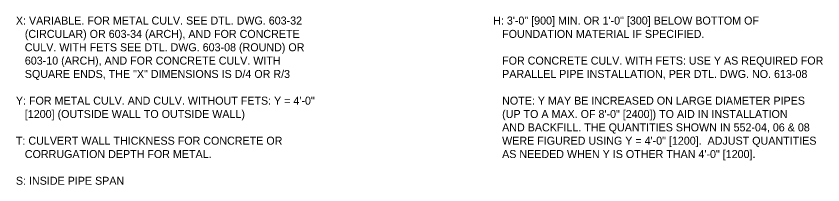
# Model space of a CAD drawing. Extents: x 49988.5 to 50021, y 49987.6 to 50011.4.
# Drawn here: x 49988.46 to 49994.5, y 50007.36 to 50008.62 of the extents above; entities that cross this region are included whole.
import ezdxf

# ---------------------------------------------------------------- set-up
doc = ezdxf.new("R2010")
doc.units = 0
doc.layers.add('Level 2', color=7, linetype='Continuous')

msp = doc.modelspace()

# ---------------------------------------------------------------- texts
at = {"layer": 'Level 2'}
for s, p in [('X: VARIABLE. FOR METAL CULV. SEE DTL. DWG. 603-32 ', (49988.456, 50008.5609)), ('H: 3\'-0" [900] MIN. OR 1\'-0" [300] BELOW BOTTOM OF', (49992.0327, 50008.5609)), ('   (CIRCULAR) OR 603-34 (ARCH), AND FOR CONCRETE ', (49988.456, 50008.4609)), ('   FOUNDATION MATERIAL IF SPECIFIED.', (49992.0327, 50008.4609)), ('   CULV. WITH FETS SEE DTL. DWG. 603-08 (ROUND) OR ', (49988.456, 50008.3609)), ('   603-10 (ARCH), AND FOR CONCRETE CULV. WITH ', (49988.456, 50008.2609)), ('   FOR CONCRETE CULV. WITH FETS: USE Y AS REQUIRED FOR', (49992.0327, 50008.2609)), ('   SQUARE ENDS, THE "X" DIMENSIONS IS D/4 OR R/3', (49988.456, 50008.1609)), ('   PARALLEL PIPE INSTALLATION, PER DTL. DWG. NO. 613-08', (49992.0327, 50008.1609)), ('Y: FOR METAL CULV. AND CULV. WITHOUT FETS: Y = 4\'-0"', (49988.456, 50007.9609)), ('   NOTE: Y MAY BE INCREASED ON LARGE DIAMETER PIPES', (49992.0327, 50007.9609)), ('   [1200] (OUTSIDE WALL TO OUTSIDE WALL)', (49988.456, 50007.8609)), ('   (UP TO A MAX. OF 8\'-0" [2400]) TO AID IN INSTALLATION', (49992.0327, 50007.8609)), ('   AND BACKFILL. THE QUANTITIES SHOWN IN 552-04, 06 & 08', (49992.0327, 50007.7609)), ('T: CULVERT WALL THICKNESS FOR CONCRETE OR', (49988.456, 50007.6609)), ('   WERE FIGURED USING Y = 4\'-0" [1200].  ADJUST QUANTITIES', (49992.0327, 50007.6609)), ('   CORRUGATION DEPTH FOR METAL.', (49988.456, 50007.5609)), ('   AS NEEDED WHEN Y IS OTHER THAN 4\'-0" [1200].  ', (49992.0327, 50007.5609)), ('S: INSIDE PIPE SPAN', (49988.456, 50007.3609))]:
    msp.add_text(s, height=0.06, dxfattribs=at).set_placement(p)

doc.saveas('drawing.dxf')
